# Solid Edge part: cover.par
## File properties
Author: Robert a Rhodes jr
Template: NORMENG.PAR
Last saved by: CADCIM
Revision: 13
Application: Solid Edge
Accuracy: 0.99
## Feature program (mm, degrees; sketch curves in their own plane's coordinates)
sketch for "unnamed Protrusion 1" plane through (0, 0, 0) normal (0, 0, 1) x-axis (1, 0, 0)
  line (0, 0) -> (0, 0)
  circle centre (0, 0) radius 88.9
extrude "unnamed Protrusion 1" add finite 63.5 along -normal
fillet "Round_1" radius 25.4
thinwall "Thinwall_1"  Thickness = 6.35 mm
sketch for "ExtrudedProtrusion_3" #1 plane through (-1.5818, 0.3164, -63.5) normal (0, 0, -1) x-axis (-1, 0, 0)
  circle centre (-1.5818, 107.6336) radius 9.525
sketch for "ExtrudedProtrusion_3" #2 plane through (-1.5818, 0.3164, -63.5) normal (0, 0, -1) x-axis (-1, 0, 0)
  line (-20.6318, 86.5186) -> (-20.6318, 107.6336)
  arc centre (-1.5818, 107.6336) radius 19.05 from (-20.6318, 107.6336) to (17.4682, 107.6336) cw
  line (17.4682, 107.6336) -> (17.4682, 86.5186)
  arc centre (-1.5818, -0.3164) radius 88.9 from (17.4682, 86.5186) to (-20.6318, 86.5186) ccw
extrude "ExtrudedProtrusion_3" add finite 12.7 along -normal
pattern "unnamed Pattern 1" of "ExtrudedProtrusion_3"
extrude "unnamed Protrusion 2" add finite 12.7
extrude "unnamed Protrusion 3" add finite 12.7
sketch for "ExtrudedProtrusion_6" plane through (0, 0, 0) normal (0, 0, 1) x-axis (1, 0, 0)
  circle centre (0, 0) radius 31.75
extrude "ExtrudedProtrusion_6" add finite 19.05 along +normal
fillet "Round_2" radius 5.08
sketch used by "unnamed Cutout 1" plane through (0, 0, 0) normal (0, 0, 1) x-axis (1, 0, 0)
extrude "unnamed Cutout 1" cut through along -normal
pattern "unnamed Pattern 2" of "unnamed Cutout 1"
extrude "unnamed Cutout 2" cut through
extrude "unnamed Cutout 3" cut through
extrude "unnamed Cutout 4" cut through
extrude "unnamed Cutout 5" cut through
extrude "unnamed Cutout 6" cut through
extrude "unnamed Cutout 7" cut through
sketch for "unnamed Protrusion 4" plane through (0, 0, 0) normal (0, 0, -1) x-axis (0, -1, 0)
  circle centre (0, 0) radius 31.75
extrude "unnamed Protrusion 4" add along +normal
sketch for "Hole_1" plane through (0, 0, 19.05) normal (0, 0, 1) x-axis (1, 0, 0)
  hole centre (0, 0) bore radius 19.05
hole "Hole_1" diameter 38.1 through
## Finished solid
Body 1: solid body, 66 faces, 205 edges, 128 vertices.
  Faces by surface: plane 39, cylinder 24, torus 3
  Edges by curve: line 112, circle 69, intersection 24
Bounding box of the edges (mm; curved faces can reach further): 225.075 x 215.900 x 82.550, from (-112.5374, -88.9, -63.5) to (112.5374, 127, 19.05).
Cylindrical faces by radius (mm): R3.81 x14, R9.525 x3, R19.05 x4, R31.75 x1, R82.55 x1, R88.9 x1
Toroidal faces (ring radius, tube radius in mm): R26.67 r5.08 x1, R63.5 r19.05 x1, R63.5 r25.4 x1
Planar faces by outward normal: +x 12, +z 7, -x 12, -z 4, oblique 4
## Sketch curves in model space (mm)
arc centre (-45.72, -50.8, 0) radius 3.81 from (-41.91, -50.8, 0) through (-45.8329, -54.6083, 0) to (-49.53, -50.8, 0)
line (-49.53, -50.8, 0) -> (-49.53, 50.8, 0)
arc centre (-45.72, 50.8, 0) radius 3.81 from (-49.53, 50.8, 0) through (-45.6071, 54.6083, 0) to (-41.91, 50.8, 0)
line (-41.91, 50.8, 0) -> (-41.91, -50.8, 0)
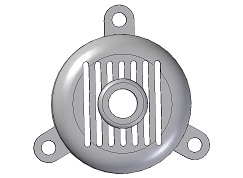
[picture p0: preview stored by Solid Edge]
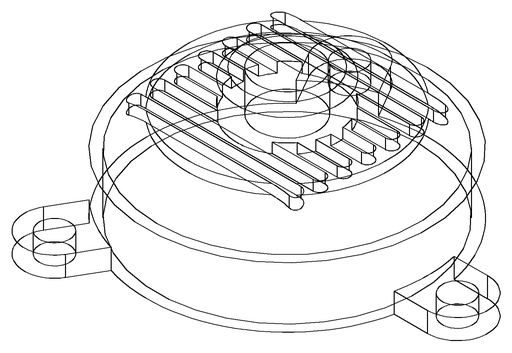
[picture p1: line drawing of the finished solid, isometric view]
